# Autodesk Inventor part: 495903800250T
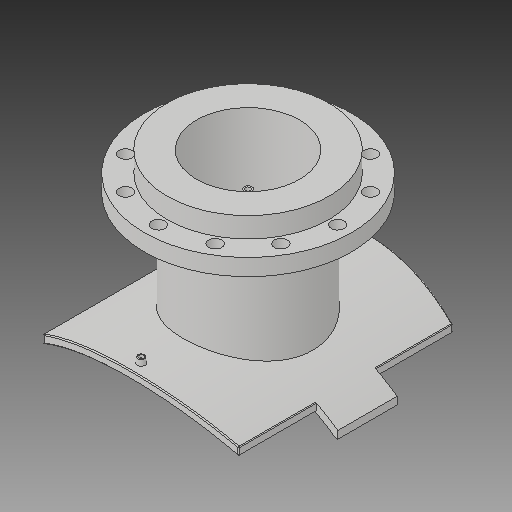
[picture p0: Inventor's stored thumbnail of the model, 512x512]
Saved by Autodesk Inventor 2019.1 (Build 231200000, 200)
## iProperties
Created: 2017-10
Part Number: 495903800250T
Material: Generic
Description: PLASSON FLANGED BRANCH SADDLE 800X250
Document SubType Name: Modeling
Designer: KIM
Mass: 2339.99 g
Surface Area: 3251.55 cm^2
Volume: 2339.99 cm^3
Density: 1 g/cm^3
Appearance: Default
Author: KIM
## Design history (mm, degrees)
derived "495904_495903.ipt"
feature "Solid1::495904_495903.ipt"
feature "Solid2::495904_495903.ipt"
tag "TaggingFeature1"
body "Solid1"
other parameters: "d1" = 15, "d2" = 387, "d4" = 0, "d6" = 117.5, "d7" = 0, "d12" = 425.6, "d13" = 14, "d14" = 211.5, "d16" = 5 deg, "d18" = 4, "d19" = 14, "d20" = 0, "d21" = 3, "d22" = 0, "d36" = 211.5, "d38" = 0, "d39" = 2, "d41" = 204, "d46" = 256, "d47" = 16, "d48" = 10.4, "d49" = 192.5, "d51" = 816, "d53" = 0, "d54" = 26, "d55" = 177.5, "d57" = 0, "d59" = 360 deg, "d61" = 33, "d63" = 0, "d66" = 275, "d67" = 15, "d68" = 137.5, "d70" = 0, "d71" = 2, "H_" = 275, "x_" = 15, "D_" = 16, "DN_" = 204, "t_" = 33, "s_" = 26, "Dp_" = 355
